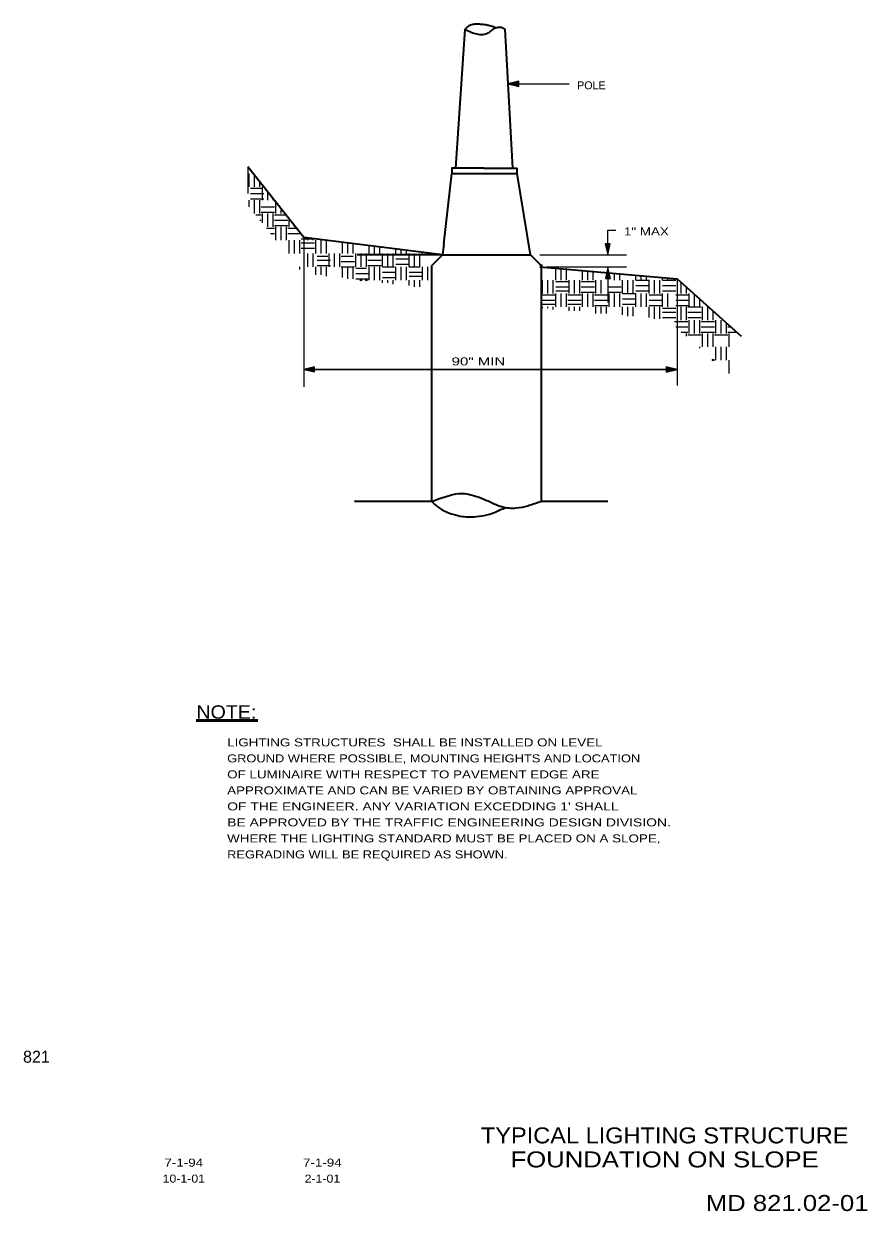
# Model space of a CAD drawing. Extents: x 9987.92 to 9994.25, y 10009.13 to 10018.04.
import ezdxf
from ezdxf.enums import TextEntityAlignment as Align

# ---------------------------------------------------------------- set-up
doc = ezdxf.new("R2010")
doc.units = 0
doc.header["$LTSCALE"] = 0.024
doc.header["$PDMODE"] = 32
doc.header["$PDSIZE"] = 0.012
for name, color, linetype, lineweight in [('1', 7, 'Continuous', 35), ('10', 7, 'Continuous', 13), ('13', 7, 'Continuous', 53), ('6', 7, 'Continuous', 13)]:
    doc.layers.add(name, color=color, linetype=linetype, lineweight=lineweight)
doc.layers.add('12', color=7, linetype='Continuous')

msp = doc.modelspace()

# ---------------------------------------------------------------- linework, layer by layer
at = {"layer": '1'}
for p, q in [((9991.163, 10016.954), (9991.233, 10017.994)), ((9991.592, 10016.954), (9991.533, 10017.994)), ((9991.073, 10016.384), (9991.133, 10016.914)), ((9991.373, 10016.954), (9991.623, 10016.954)), ((9991.723, 10016.304), (9991.623, 10016.914)), ((9991.073, 10016.384), (9991.063, 10016.304)), ((9991.053, 10016.304), (9990.423, 10016.304)), ((9991.063, 10016.304), (9990.983, 10016.224)), ((9991.063, 10016.304), (9991.723, 10016.304)), ((9991.723, 10016.304), (9991.803, 10016.224)), ((9990.983, 10014.454), (9990.983, 10016.224)), ((9991.803, 10016.224), (9991.803, 10014.454)), ((9990.983, 10014.454), (9990.403, 10014.454)), ((9991.803, 10014.454), (9991.801, 10014.454)), ((9992.303, 10014.454), (9991.803, 10014.454))]:
    msp.add_line(p, q, dxfattribs=at)
for points in [[(9991.063, 10016.304), (9990.023, 10016.434), (9989.603, 10016.964)], [(9991.373, 10016.954), (9991.133, 10016.954), (9991.133, 10016.914), (9991.623, 10016.914), (9991.623, 10016.954)], [(9991.793, 10016.214), (9992.823, 10016.124), (9993.303, 10015.694)]]:
    msp.add_lwpolyline(points, dxfattribs=at)
for points in [[(9991.233, 10017.994), (9991.264, 10018.029), (9991.31, 10018.037), (9991.351, 10018.033), (9991.384, 10018.031), (9991.409, 10018.024), (9991.428, 10018.02), (9991.442, 10018.016), (9991.454, 10018.008), (9991.461, 10018.007)], [(9991.233, 10017.994), (9991.285, 10017.968), (9991.349, 10017.949), (9991.39, 10017.959), (9991.422, 10017.975), (9991.438, 10017.994), (9991.46, 10018.005), (9991.482, 10018.011), (9991.501, 10018.011), (9991.51, 10018.007), (9991.521, 10018.001), (9991.533, 10017.994)], [(9990.983, 10014.454), (9991.155, 10014.519), (9991.248, 10014.519), (9991.394, 10014.465), (9991.511, 10014.406), (9991.618, 10014.401), (9991.708, 10014.42), (9991.752, 10014.439), (9991.801, 10014.454)], [(9990.983, 10014.454), (9991.045, 10014.387), (9991.177, 10014.342), (9991.282, 10014.335), (9991.357, 10014.345), (9991.435, 10014.359), (9991.482, 10014.387), (9991.533, 10014.406)]]:
    msp.add_open_spline(points, degree=3, dxfattribs=at)
at = {"layer": '10'}
for p, q in [((9991.553, 10017.584), (9992.013, 10017.584)), ((9992.303, 10016.304), (9992.303, 10016.488)), ((9992.303, 10016.488), (9992.363, 10016.488)), ((9990.023, 10016.434), (9990.023, 10015.312)), ((9991.793, 10016.304), (9992.443, 10016.304)), ((9991.843, 10016.214), (9992.443, 10016.214)), ((9992.303, 10016.208), (9992.303, 10015.945)), ((9992.823, 10016.124), (9992.823, 10015.324)), ((9990.023, 10015.444), (9992.823, 10015.444)), ((9992.763, 10015.444), (9990.083, 10015.444))]:
    msp.add_line(p, q, dxfattribs=at)
for points in [[(9991.635, 10017.604), (9991.553, 10017.584), (9991.635, 10017.566)], [(9991.633, 10017.601), (9991.561, 10017.584), (9991.633, 10017.568)], [(9991.631, 10017.599), (9991.569, 10017.584), (9991.631, 10017.57)], [(9991.63, 10017.597), (9991.577, 10017.584), (9991.63, 10017.573)], [(9991.628, 10017.595), (9991.584, 10017.584), (9991.628, 10017.575)], [(9991.626, 10017.592), (9991.593, 10017.584), (9991.626, 10017.577)], [(9991.624, 10017.59), (9991.6, 10017.584), (9991.624, 10017.579)], [(9991.623, 10017.588), (9991.608, 10017.585), (9991.623, 10017.581)], [(9991.621, 10017.586), (9991.616, 10017.585), (9991.621, 10017.584)], [(9992.283, 10016.386), (9992.303, 10016.304), (9992.321, 10016.386)], [(9992.286, 10016.384), (9992.303, 10016.312), (9992.319, 10016.384)], [(9992.288, 10016.382), (9992.303, 10016.32), (9992.317, 10016.382)], [(9992.29, 10016.381), (9992.303, 10016.328), (9992.314, 10016.381)], [(9992.292, 10016.379), (9992.303, 10016.335), (9992.312, 10016.379)], [(9992.295, 10016.377), (9992.303, 10016.344), (9992.31, 10016.377)], [(9992.297, 10016.375), (9992.303, 10016.351), (9992.308, 10016.375)], [(9992.299, 10016.374), (9992.302, 10016.359), (9992.306, 10016.374)], [(9992.301, 10016.372), (9992.302, 10016.367), (9992.303, 10016.372)], [(9992.323, 10016.126), (9992.303, 10016.208), (9992.285, 10016.126)], [(9992.32, 10016.128), (9992.303, 10016.2), (9992.287, 10016.128)], [(9992.318, 10016.13), (9992.303, 10016.192), (9992.289, 10016.13)], [(9992.316, 10016.131), (9992.303, 10016.184), (9992.292, 10016.131)], [(9992.314, 10016.133), (9992.303, 10016.177), (9992.294, 10016.133)], [(9992.311, 10016.135), (9992.303, 10016.168), (9992.296, 10016.135)], [(9992.309, 10016.137), (9992.303, 10016.161), (9992.298, 10016.137)], [(9992.307, 10016.138), (9992.304, 10016.153), (9992.3, 10016.138)], [(9992.305, 10016.14), (9992.304, 10016.145), (9992.303, 10016.14)], [(9990.105, 10015.464), (9990.023, 10015.444), (9990.105, 10015.426)], [(9990.103, 10015.461), (9990.031, 10015.444), (9990.103, 10015.428)], [(9990.101, 10015.459), (9990.039, 10015.444), (9990.101, 10015.43)], [(9990.1, 10015.457), (9990.047, 10015.444), (9990.1, 10015.433)], [(9990.098, 10015.455), (9990.054, 10015.444), (9990.098, 10015.435)], [(9990.096, 10015.452), (9990.063, 10015.444), (9990.096, 10015.437)], [(9990.094, 10015.45), (9990.07, 10015.444), (9990.094, 10015.439)], [(9990.093, 10015.448), (9990.078, 10015.445), (9990.093, 10015.441)], [(9990.091, 10015.446), (9990.086, 10015.445), (9990.091, 10015.444)]]:
    msp.add_lwpolyline(points, close=True, dxfattribs=at)
at = {"layer": '13'}
msp.add_line((9989.217, 10012.81), (9989.678, 10012.81), dxfattribs=at)
at = {"layer": '6'}
for p, q in [((9989.603, 10016.964), (9989.603, 10016.764)), ((9989.613, 10016.814), (9989.613, 10016.914)), ((9989.653, 10016.814), (9989.653, 10016.904)), ((9989.623, 10016.804), (9989.713, 10016.804)), ((9989.693, 10016.814), (9989.693, 10016.854)), ((9989.713, 10016.714), (9989.713, 10016.814)), ((9989.613, 10016.664), (9989.613, 10016.714)), ((9989.623, 10016.764), (9989.723, 10016.764)), ((9989.623, 10016.724), (9989.723, 10016.724)), ((9989.653, 10016.614), (9989.653, 10016.714)), ((9989.693, 10016.614), (9989.693, 10016.714)), ((9989.753, 10016.714), (9989.753, 10016.774)), ((9989.793, 10016.714), (9989.793, 10016.724)), ((9989.703, 10016.664), (9989.803, 10016.664)), ((9989.703, 10016.624), (9989.803, 10016.624)), ((9989.813, 10016.614), (9989.813, 10016.694)), ((9989.853, 10016.614), (9989.853, 10016.644)), ((9989.663, 10016.604), (9989.703, 10016.604)), ((9989.693, 10016.564), (9989.703, 10016.564)), ((9989.713, 10016.544), (9989.713, 10016.614)), ((9989.753, 10016.514), (9989.753, 10016.614)), ((9989.793, 10016.514), (9989.793, 10016.614)), ((9989.803, 10016.604), (9989.893, 10016.604)), ((9989.803, 10016.564), (9989.903, 10016.564)), ((9989.913, 10016.514), (9989.913, 10016.564)), ((9989.743, 10016.504), (9989.803, 10016.504)), ((9989.773, 10016.464), (9989.803, 10016.464)), ((9989.803, 10016.524), (9989.903, 10016.524)), ((9989.813, 10016.414), (9989.813, 10016.514)), ((9989.853, 10016.414), (9989.853, 10016.514)), ((9989.893, 10016.414), (9989.893, 10016.514)), ((9989.903, 10016.504), (9989.963, 10016.504)), ((9989.903, 10016.464), (9990.003, 10016.464)), ((9989.953, 10016.514), (9989.953, 10016.524)), ((9989.913, 10016.314), (9989.913, 10016.414)), ((9989.953, 10016.314), (9989.953, 10016.414)), ((9989.993, 10016.314), (9989.993, 10016.414)), ((9990.003, 10016.424), (9990.093, 10016.424)), ((9990.003, 10016.394), (9990.103, 10016.394)), ((9990.003, 10016.354), (9990.103, 10016.354)), ((9990.053, 10016.414), (9990.053, 10016.434)), ((9990.093, 10016.414), (9990.093, 10016.424)), ((9990.113, 10016.314), (9990.113, 10016.414)), ((9990.153, 10016.314), (9990.153, 10016.414)), ((9990.193, 10016.314), (9990.193, 10016.414)), ((9990.313, 10016.314), (9990.313, 10016.394)), ((9990.353, 10016.314), (9990.353, 10016.394)), ((9990.393, 10016.314), (9990.393, 10016.384)), ((9990.513, 10016.314), (9990.513, 10016.374)), ((9990.553, 10016.314), (9990.553, 10016.364)), ((9990.593, 10016.314), (9990.593, 10016.364)), ((9990.053, 10016.214), (9990.053, 10016.314)), ((9990.093, 10016.214), (9990.093, 10016.314)), ((9990.123, 10016.294), (9990.203, 10016.294)), ((9990.123, 10016.264), (9990.223, 10016.264)), ((9990.213, 10016.214), (9990.213, 10016.314)), ((9990.253, 10016.214), (9990.253, 10016.314)), ((9990.293, 10016.214), (9990.293, 10016.314)), ((9990.303, 10016.294), (9990.393, 10016.294)), ((9990.413, 10016.214), (9990.413, 10016.314)), ((9990.453, 10016.214), (9990.453, 10016.314)), ((9990.493, 10016.214), (9990.493, 10016.314)), ((9990.503, 10016.304), (9990.593, 10016.304)), ((9990.503, 10016.264), (9990.603, 10016.264)), ((9990.613, 10016.214), (9990.613, 10016.314)), ((9990.653, 10016.214), (9990.653, 10016.314)), ((9990.693, 10016.214), (9990.693, 10016.314)), ((9990.713, 10016.314), (9990.713, 10016.344)), ((9990.713, 10016.304), (9990.803, 10016.304)), ((9990.713, 10016.274), (9990.813, 10016.274)), ((9990.753, 10016.314), (9990.753, 10016.344)), ((9990.793, 10016.314), (9990.793, 10016.344)), ((9990.813, 10016.214), (9990.813, 10016.314)), ((9990.853, 10016.214), (9990.853, 10016.314)), ((9990.893, 10016.214), (9990.893, 10016.314)), ((9990.913, 10016.314), (9990.913, 10016.324)), ((9990.953, 10016.314), (9990.953, 10016.324)), ((9989.993, 10016.194), (9989.993, 10016.214)), ((9990.113, 10016.154), (9990.113, 10016.214)), ((9990.123, 10016.224), (9990.223, 10016.224)), ((9990.153, 10016.154), (9990.153, 10016.214)), ((9990.193, 10016.144), (9990.193, 10016.214)), ((9990.303, 10016.254), (9990.403, 10016.254)), ((9990.303, 10016.214), (9990.403, 10016.214)), ((9990.313, 10016.134), (9990.313, 10016.214)), ((9990.353, 10016.124), (9990.353, 10016.214)), ((9990.393, 10016.124), (9990.393, 10016.214)), ((9990.413, 10016.204), (9990.493, 10016.204)), ((9990.503, 10016.224), (9990.603, 10016.224)), ((9990.513, 10016.114), (9990.513, 10016.214)), ((9990.553, 10016.114), (9990.553, 10016.214)), ((9990.593, 10016.114), (9990.593, 10016.214)), ((9990.613, 10016.214), (9990.703, 10016.214)), ((9990.613, 10016.174), (9990.713, 10016.174)), ((9990.713, 10016.234), (9990.813, 10016.234)), ((9990.713, 10016.114), (9990.713, 10016.214)), ((9990.753, 10016.114), (9990.753, 10016.214)), ((9990.793, 10016.114), (9990.793, 10016.214)), ((9990.813, 10016.214), (9990.893, 10016.214)), ((9990.813, 10016.174), (9990.913, 10016.174)), ((9990.913, 10016.114), (9990.913, 10016.214)), ((9990.953, 10016.114), (9990.953, 10016.214)), ((9991.913, 10016.114), (9991.913, 10016.204)), ((9991.953, 10016.114), (9991.953, 10016.204)), ((9991.993, 10016.114), (9991.993, 10016.204)), ((9992.113, 10016.114), (9992.113, 10016.184)), ((9992.153, 10016.114), (9992.153, 10016.184)), ((9992.193, 10016.114), (9992.193, 10016.184)), ((9990.413, 10016.164), (9990.513, 10016.164)), ((9990.413, 10016.124), (9990.513, 10016.124)), ((9990.613, 10016.134), (9990.713, 10016.134)), ((9990.613, 10016.094), (9990.613, 10016.114)), ((9990.653, 10016.094), (9990.653, 10016.114)), ((9990.693, 10016.084), (9990.693, 10016.114)), ((9990.813, 10016.144), (9990.913, 10016.144)), ((9990.813, 10016.074), (9990.813, 10016.114)), ((9990.853, 10016.064), (9990.853, 10016.114)), ((9990.893, 10016.064), (9990.893, 10016.114)), ((9991.813, 10016.014), (9991.813, 10016.114)), ((9991.853, 10016.014), (9991.853, 10016.114)), ((9991.893, 10016.014), (9991.893, 10016.114)), ((9991.913, 10016.104), (9992.013, 10016.104)), ((9992.013, 10016.014), (9992.013, 10016.114)), ((9992.053, 10016.014), (9992.053, 10016.114)), ((9992.093, 10016.014), (9992.093, 10016.114)), ((9992.103, 10016.104), (9992.203, 10016.104)), ((9992.213, 10016.014), (9992.213, 10016.114)), ((9992.253, 10016.014), (9992.253, 10016.114)), ((9992.353, 10016.114), (9992.353, 10016.164)), ((9992.393, 10016.114), (9992.393, 10016.164)), ((9992.413, 10016.014), (9992.413, 10016.114)), ((9992.453, 10016.014), (9992.453, 10016.114)), ((9992.493, 10016.014), (9992.493, 10016.114)), ((9992.513, 10016.114), (9992.513, 10016.144)), ((9992.513, 10016.114), (9992.613, 10016.114)), ((9992.553, 10016.114), (9992.553, 10016.144)), ((9992.593, 10016.114), (9992.593, 10016.144)), ((9992.613, 10016.014), (9992.613, 10016.114)), ((9992.653, 10016.014), (9992.653, 10016.114)), ((9992.693, 10016.014), (9992.693, 10016.114)), ((9992.713, 10016.114), (9992.713, 10016.134)), ((9992.713, 10016.114), (9992.813, 10016.114)), ((9992.753, 10016.114), (9992.753, 10016.124)), ((9992.853, 10016.014), (9992.853, 10016.094)), ((9991.813, 10016.004), (9991.913, 10016.004)), ((9991.913, 10016.064), (9992.013, 10016.064)), ((9991.913, 10016.034), (9992.013, 10016.034)), ((9991.913, 10015.914), (9991.913, 10016.014)), ((9991.953, 10015.914), (9991.953, 10016.014)), ((9991.993, 10015.914), (9991.993, 10016.014)), ((9992.003, 10016.004), (9992.103, 10016.004)), ((9992.103, 10016.064), (9992.203, 10016.064)), ((9992.103, 10016.024), (9992.203, 10016.024)), ((9992.113, 10015.914), (9992.113, 10016.014)), ((9992.153, 10015.914), (9992.153, 10016.014)), ((9992.193, 10015.914), (9992.193, 10016.014)), ((9992.203, 10016.004), (9992.303, 10016.004)), ((9992.303, 10016.064), (9992.403, 10016.064)), ((9992.303, 10016.024), (9992.403, 10016.024)), ((9992.313, 10015.914), (9992.313, 10016.014)), ((9992.353, 10015.914), (9992.353, 10016.014)), ((9992.393, 10015.914), (9992.393, 10016.014)), ((9992.413, 10016.014), (9992.513, 10016.014)), ((9992.513, 10016.074), (9992.613, 10016.074)), ((9992.513, 10016.034), (9992.613, 10016.034)), ((9992.513, 10015.914), (9992.513, 10016.014)), ((9992.553, 10015.914), (9992.553, 10016.014)), ((9992.593, 10015.914), (9992.593, 10016.014)), ((9992.613, 10016.004), (9992.713, 10016.004)), ((9992.713, 10016.074), (9992.813, 10016.074)), ((9992.713, 10016.034), (9992.813, 10016.034)), ((9992.713, 10015.914), (9992.713, 10016.014)), ((9992.753, 10015.914), (9992.753, 10016.014)), ((9992.813, 10016.004), (9992.913, 10016.004)), ((9992.893, 10016.014), (9992.893, 10016.064)), ((9992.913, 10015.914), (9992.913, 10016.014)), ((9992.953, 10015.914), (9992.953, 10016.004)), ((9991.813, 10015.964), (9991.913, 10015.964)), ((9991.813, 10015.934), (9991.913, 10015.934)), ((9991.813, 10015.904), (9991.813, 10015.914)), ((9991.853, 10015.904), (9991.853, 10015.914)), ((9991.893, 10015.894), (9991.893, 10015.914)), ((9992.003, 10015.964), (9992.103, 10015.964)), ((9992.003, 10015.934), (9992.103, 10015.934)), ((9992.013, 10015.884), (9992.013, 10015.914)), ((9992.053, 10015.884), (9992.053, 10015.914)), ((9992.093, 10015.884), (9992.093, 10015.914)), ((9992.203, 10015.964), (9992.303, 10015.964)), ((9992.203, 10015.924), (9992.303, 10015.924)), ((9992.213, 10015.864), (9992.213, 10015.914)), ((9992.253, 10015.864), (9992.253, 10015.914)), ((9992.293, 10015.864), (9992.293, 10015.914)), ((9992.413, 10015.974), (9992.513, 10015.974)), ((9992.413, 10015.934), (9992.513, 10015.934)), ((9992.413, 10015.854), (9992.413, 10015.914)), ((9992.453, 10015.844), (9992.453, 10015.914)), ((9992.493, 10015.844), (9992.493, 10015.914)), ((9992.613, 10015.964), (9992.713, 10015.964)), ((9992.613, 10015.924), (9992.713, 10015.924)), ((9992.613, 10015.834), (9992.613, 10015.914)), ((9992.653, 10015.824), (9992.653, 10015.914)), ((9992.693, 10015.824), (9992.693, 10015.914)), ((9992.713, 10015.904), (9992.813, 10015.904)), ((9992.813, 10015.964), (9992.913, 10015.964)), ((9992.813, 10015.924), (9992.913, 10015.924)), ((9992.853, 10015.814), (9992.853, 10015.914)), ((9992.893, 10015.814), (9992.893, 10015.914)), ((9992.903, 10015.914), (9993.003, 10015.914)), ((9992.993, 10015.914), (9992.993, 10015.974)), ((9993.013, 10015.814), (9993.013, 10015.914)), ((9993.053, 10015.814), (9993.053, 10015.914)), ((9992.713, 10015.874), (9992.813, 10015.874)), ((9992.713, 10015.834), (9992.813, 10015.834)), ((9992.903, 10015.874), (9993.003, 10015.874)), ((9992.903, 10015.834), (9993.003, 10015.834)), ((9992.913, 10015.714), (9992.913, 10015.814)), ((9992.953, 10015.714), (9992.953, 10015.814)), ((9992.993, 10015.714), (9992.993, 10015.814)), ((9993.093, 10015.814), (9993.093, 10015.884)), ((9993.113, 10015.714), (9993.113, 10015.814)), ((9993.153, 10015.714), (9993.153, 10015.814)), ((9992.803, 10015.804), (9992.903, 10015.804)), ((9992.813, 10015.764), (9992.903, 10015.764)), ((9993.003, 10015.804), (9993.103, 10015.804)), ((9993.003, 10015.764), (9993.103, 10015.764)), ((9993.193, 10015.714), (9993.193, 10015.794)), ((9993.203, 10015.764), (9993.223, 10015.764)), ((9992.853, 10015.724), (9992.903, 10015.724)), ((9992.893, 10015.694), (9992.893, 10015.714)), ((9992.903, 10015.704), (9993.003, 10015.704)), ((9993.003, 10015.724), (9993.103, 10015.724)), ((9993.013, 10015.614), (9993.013, 10015.714)), ((9993.053, 10015.614), (9993.053, 10015.714)), ((9993.093, 10015.614), (9993.093, 10015.714)), ((9993.103, 10015.704), (9993.203, 10015.704)), ((9993.203, 10015.724), (9993.263, 10015.724)), ((9993.213, 10015.614), (9993.213, 10015.714)), ((9992.993, 10015.604), (9992.993, 10015.614)), ((9993.113, 10015.514), (9993.113, 10015.614)), ((9993.153, 10015.514), (9993.153, 10015.614)), ((9993.193, 10015.514), (9993.193, 10015.614)), ((9993.213, 10015.414), (9993.213, 10015.514))]:
    msp.add_line(p, q, dxfattribs=at)
for points in [[(9992.741, 10015.424), (9992.823, 10015.444), (9992.741, 10015.462)], [(9992.743, 10015.427), (9992.815, 10015.444), (9992.743, 10015.46)], [(9992.745, 10015.429), (9992.807, 10015.444), (9992.745, 10015.458)], [(9992.746, 10015.431), (9992.799, 10015.444), (9992.746, 10015.455)], [(9992.748, 10015.433), (9992.792, 10015.444), (9992.748, 10015.453)], [(9992.75, 10015.436), (9992.783, 10015.444), (9992.75, 10015.451)], [(9992.752, 10015.438), (9992.776, 10015.444), (9992.752, 10015.449)], [(9992.753, 10015.44), (9992.768, 10015.443), (9992.753, 10015.447)], [(9992.755, 10015.442), (9992.76, 10015.443), (9992.755, 10015.444)]]:
    msp.add_lwpolyline(points, close=True, dxfattribs=at)
for p in [(9991.063, 10016.304), (9991.803, 10016.224), (9990.453, 10016.114), (9990.493, 10016.114), (9993.093, 10015.514)]:
    msp.add_point(p, dxfattribs=at)

# ---------------------------------------------------------------- texts
at = {"layer": '12'}
msp.add_text('POLE', height=0.06, dxfattribs=at).set_placement((9992.073, 10017.544))
for s, width, p in [('1" MAX', 1.25, (9992.424, 10016.448)), ('90" MIN', 1.4, (9991.132, 10015.474))]:
    msp.add_text(s, height=0.06, dxfattribs=dict(at, width=width)).set_placement(p)
at = {"layer": '13'}
for s, height, width, p in [('NOTE:', 0.1, 1.1, (9989.443, 10012.825)), ('TYPICAL LIGHTING STRUCTURE', 0.12, 1.1, (9992.7295, 10009.64)), ('FOUNDATION ON SLOPE', 0.12, 1.2, (9992.729, 10009.46)), ('7-1-94', 0.06, 1.25, (9989.1235, 10009.466)), ('7-1-94', 0.06, 1.25, (9990.1625, 10009.466)), ('10-1-01', 0.06, 1.15, (9989.124, 10009.346)), ('2-1-01', 0.06, 1.15, (9990.163, 10009.346)), ('MD 821.02-01', 0.12, 1.2, (9993.6475, 10009.133))]:
    msp.add_text(s, height=height, dxfattribs=dict(at, width=width)).set_placement(p, align=Align.CENTER)
for s, width, p in [('LIGHTING STRUCTURES  SHALL BE INSTALLED ON LEVEL', 1.25, (9989.449, 10012.617)), ('GROUND WHERE POSSIBLE, MOUNTING HEIGHTS AND LOCATION', 1.2, (9989.449, 10012.497)), ('OF LUMINAIRE WITH RESPECT TO PAVEMENT EDGE ARE', 1.25, (9989.449, 10012.377)), ('APPROXIMATE AND CAN BE VARIED BY OBTAINING APPROVAL', 1.25, (9989.449, 10012.257)), ("OF THE ENGINEER. ANY VARIATION EXCEDDING 1' SHALL", 1.3, (9989.449, 10012.137)), ('BE APPROVED BY THE TRAFFIC ENGINEERING DESIGN DIVISION.', 1.3, (9989.449, 10012.017)), ('WHERE THE LIGHTING STANDARD MUST BE PLACED ON A SLOPE,', 1.25, (9989.449, 10011.897)), ('REGRADING WILL BE REQUIRED AS SHOWN.', 1.2, (9989.449, 10011.777))]:
    msp.add_text(s, height=0.06, dxfattribs=dict(at, width=width)).set_placement(p)
msp.add_text('821', height=0.09, dxfattribs=at).set_placement((9988.019, 10010.245), align=Align.CENTER)

doc.saveas('drawing.dxf')
